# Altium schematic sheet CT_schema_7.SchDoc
size 277 x 170 mm
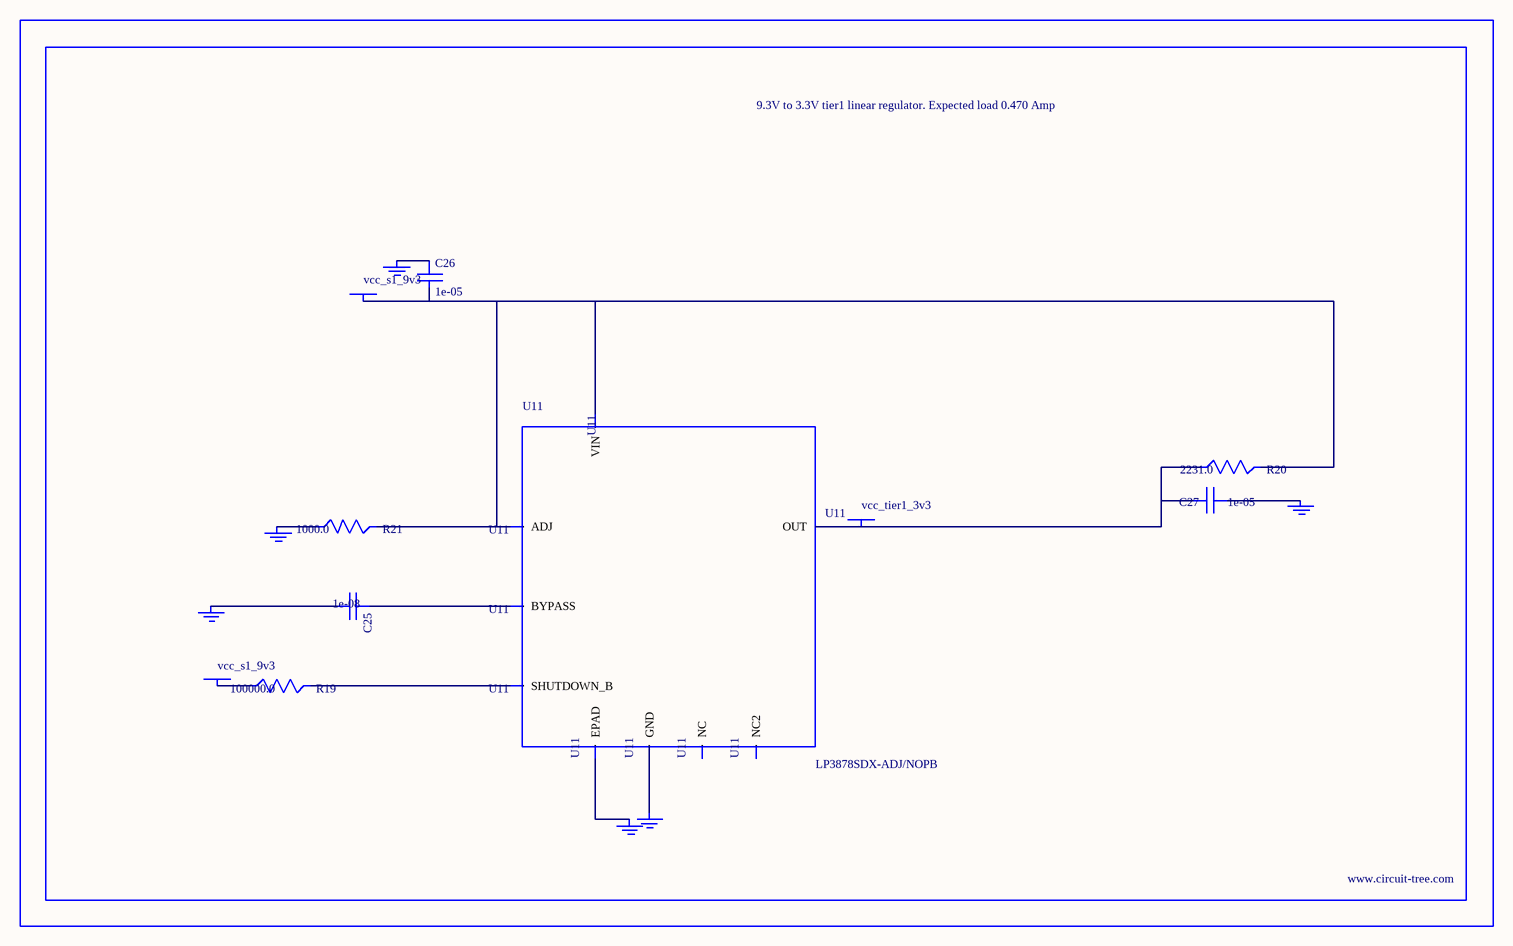
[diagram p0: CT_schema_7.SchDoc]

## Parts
BORDER6  (no value)
C25  1e-08  [C0402]
C26  1e-05  [C1206]
C27  1e-05  [C1210]
GND_INSTANCE_6_0  (no value)
GND_INSTANCE_6_1  (no value)
GND_INSTANCE_6_2  (no value)
GND_INSTANCE_6_3  (no value)
GND_INSTANCE_6_4  (no value)
GND_INSTANCE_6_5  (no value)
POWER_INSTANCE_6_0  vcc_s1_9v3
POWER_INSTANCE_6_1  vcc_s1_9v3
POWER_INSTANCE_6_2  vcc_tier1_3v3
R19  100000.0  [R0603]
R20  2231.0  [R0603]
R21  1000.0  [R0603]
U11  LP3878SDX-ADJ/NOPB  [WSON-8]

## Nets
NetC25_1: C25.1 U11.1(BYPASS)
NetC25_2: C25.2 GND_INSTANCE_6_0.0(GND)
NetC26_1: C26.1 GND_INSTANCE_6_1.0(GND)
NetC26_2: C26.2 POWER_INSTANCE_6_0.0(PWR) R20.2 R21.2 U11.4(VIN) U11.6(ADJ)
NetC27_1: C27.1 GND_INSTANCE_6_2.0(GND)
NetC27_2: C27.2 POWER_INSTANCE_6_2.0(PWR) R20.1 U11.5(OUT)
NetGND_INSTANCE_6_3_0: GND_INSTANCE_6_3.0(GND) R21.1
NetGND_INSTANCE_6_4_0: GND_INSTANCE_6_4.0(GND) U11.PAD(EPAD)
NetGND_INSTANCE_6_5_0: GND_INSTANCE_6_5.0(GND) U11.3(GND)
NetPOWER_INSTANCE_6_1_0: POWER_INSTANCE_6_1.0(PWR) R19.1
NetR19_2: R19.2 U11.8(SHUTDOWN_B)

Not connected (* = marked no-connect by the designer): U11 2(NC) 7(NC2)

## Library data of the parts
BORDER6 = BORDER_PAGE6
C25 = C0402C103K3RAC
C26 = C1206C106K3RACTU
C27 = GRM32DR61E106MA12L
GND_INSTANCE_6_0-GND_INSTANCE_6_5 = GND
POWER_INSTANCE_6_0-POWER_INSTANCE_6_2 = PWR
R19 = RC0603JR-07100KL
R20 = R20
R21 = RC0603JR-071KL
